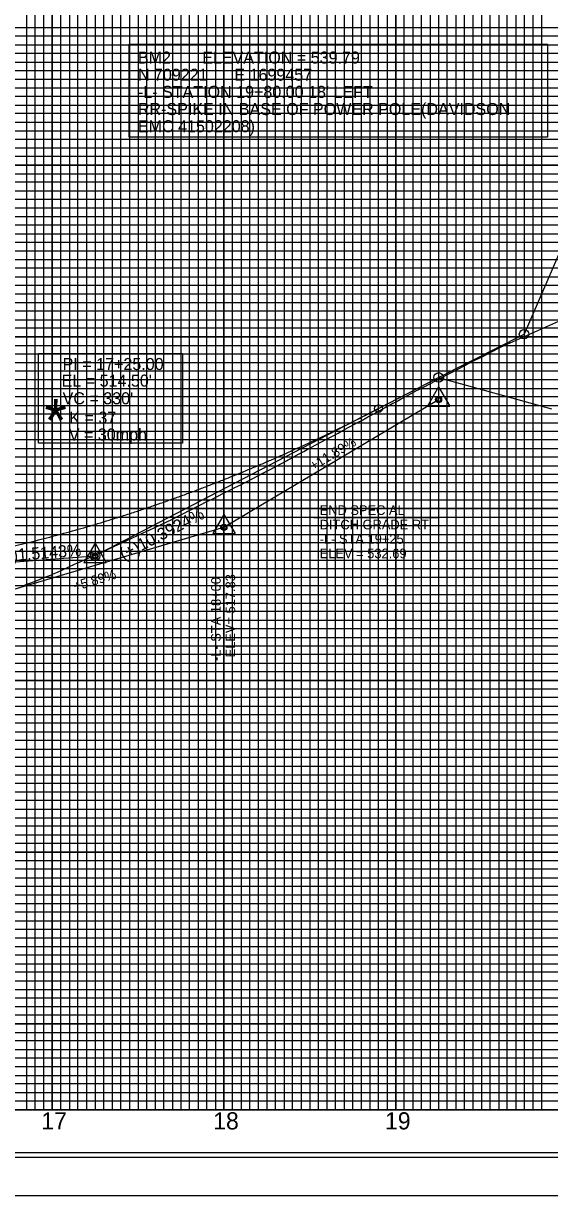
# Model space of a CAD drawing. Extents: x 573715 to 575626, y -55474 to -54374.
# Drawn here: x 574666 to 574972, y -55474 to -54792 of the extents above; entities that cross this region are included whole.
import ezdxf

# ---------------------------------------------------------------- set-up
doc = ezdxf.new("R2010")
doc.units = 0
for name, color, linetype in [('Exist Profile Cell', 7, 'Continuous'), ('Exist Vertical Profile Ground Line', 7, 'Continuous'), ('Exist Vertical Profile Horizontal Axis Label Major', 7, 'Continuous'), ('Prop Grid Mask', 7, 'Continuous'), ('Prop PFL VPI Symbol CELL', 7, 'Continuous'), ('Prop Vertical Profile Curve Label', 7, 'Continuous'), ('Prop Vertical Profile Ditch Grade Right', 7, 'Continuous'), ('Prop Vertical Profile Ditch Grade Right Label', 7, 'Continuous'), ('Prop Vertical Profile Grade', 7, 'Continuous'), ('Prop Vertical Profile Grade Label', 7, 'Continuous'), ('Prop VPI Label', 7, 'Continuous'), ('Sheet Cutting Line CELL', 7, 'Continuous'), ('Sheet DOT Grid CELL', 7, 'Continuous'), ('Sheet Layout Profile Border', 7, 'Continuous'), ('Sheet Plot Border Inside CELL', 7, 'Continuous'), ('Sheet Plot Border Outside CELL', 7, 'Continuous'), ('Sheet Profile CELL', 7, 'Continuous'), ('Sheet Profile Grid Major CELL', 7, 'Continuous'), ('Sheet Profile Grid Middle CELL', 7, 'Continuous'), ('Sheet Profile Grid Minor CELL', 7, 'Continuous')]:
    doc.layers.add(name, color=color, linetype=linetype)

msp = doc.modelspace()

# ---------------------------------------------------------------- linework, layer by layer
at = {"layer": 'Exist Profile Cell'}
msp.add_line((573982.27, -55224.42), (575001.21, -55224.42), dxfattribs=at)
at = {"layer": 'Exist Vertical Profile Ground Line'}
msp.add_lwpolyline([(574665.23, -55119.33), (574668.57, -55118.05), (574671.9, -55116.77), (574675.24, -55115.49), (574678.63, -55114.2), (574681.91, -55112.92), (574682.44, -55112.68), (574685.25, -55111.4), (574687.87, -55110.2), (574688.58, -55109.88), (574690.78, -55108.89), (574691.92, -55108.37), (574695.26, -55106.86), (574698.59, -55105.35), (574701.93, -55103.84), (574705.27, -55102.33), (574708.6, -55100.83), (574711.94, -55099.33), (574715.28, -55097.84), (574717.75, -55096.73), (574718.19, -55096.52), (574718.61, -55096.32), (574721.95, -55094.75), (574725.29, -55093.17), (574728.62, -55091.6), (574731.96, -55090.03), (574735.3, -55088.47), (574738.63, -55086.91), (574741.97, -55085.35), (574745.3, -55083.79), (574748.93, -55082.11), (574751.98, -55080.68), (574752.68, -55080.32), (574755.31, -55078.98), (574758.65, -55077.29), (574761.99, -55075.6), (574762.9, -55075.14), (574765.45, -55073.85), (574768.66, -55072.22), (574772, -55070.54), (574775.33, -55068.87), (574778.67, -55067.19), (574782.01, -55065.52), (574785.34, -55063.85), (574788.68, -55062.19), (574792.02, -55060.52), (574792.76, -55060.15), (574795.35, -55058.79), (574798.69, -55057.03), (574802.03, -55055.28), (574805.36, -55053.53), (574808.7, -55051.78), (574812.03, -55050.04), (574815.37, -55048.3), (574818.71, -55046.56), (574819.27, -55046.27), (574822.04, -55044.8), (574822.51, -55044.54), (574825.38, -55042.99), (574828.72, -55041.18), (574830.82, -55040.05), (574832.05, -55039.37), (574832.74, -55039), (574835.39, -55037.57), (574838.73, -55035.77), (574842.06, -55033.98), (574845.4, -55032.19), (574848.74, -55030.4), (574852.07, -55028.61), (574855.41, -55026.83), (574858.75, -55025.05), (574860.89, -55023.9), (574862.08, -55023.25), (574865.42, -55021.43), (574866.13, -55021.04), (574868.76, -55019.61), (574872.09, -55017.79), (574875.43, -55015.97), (574878.76, -55014.16), (574880.68, -55013.12), (574882.1, -55012.36), (574885.44, -55010.57), (574888.77, -55008.77), (574892.11, -55006.98), (574894.85, -55005.51), (574895.45, -55005.19), (574898.78, -55003.46), (574902.12, -55001.73), (574905.46, -55000), (574908.79, -54998.27), (574912.13, -54996.54), (574912.53, -54996.33), (574913.13, -54996.03), (574915.47, -54994.81), (574918.8, -54993.08), (574922.14, -54991.35), (574925.48, -54989.62), (574928.81, -54987.88), (574932.15, -54986.15), (574935.48, -54984.42), (574938.82, -54982.68), (574942.16, -54980.95), (574942.49, -54980.77), (574942.95, -54980.54), (574945.49, -54979.41), (574959.5, -54973.2), (574959.85, -54973.04), (574989.51, -54959.89)], dxfattribs=at)
at = {"layer": 'Prop Grid Mask'}
for points in [[(574727.11, -54803.99), (574970.69, -54803.99), (574970.69, -54858.09), (574727.11, -54858.09)], [(574674.23, -54984.04), (574758.07, -54984.04), (574758.07, -55036.29), (574674.23, -55036.29)]]:
    msp.add_lwpolyline(points, close=True, dxfattribs=at)
at = {"layer": 'Prop PFL VPI Symbol CELL'}
for p, q in [((574707.22, -55094.57), (574700.77, -55105.77)), ((574707.22, -55094.57), (574713.72, -55105.77)), ((574700.77, -55105.77), (574713.72, -55105.77))]:
    msp.add_line(p, q, dxfattribs=at)
for radius in [1.75, 1.2]:
    msp.add_circle((574707.23, -55102.05), radius, dxfattribs=at)
at = {"layer": 'Prop Vertical Profile Curve Label'}
for p, q in [((574987.75, -54901.88), (574957.02, -54972.88)), ((574907.27, -54998.02), (574973.06, -55016.41))]:
    msp.add_line(p, q, dxfattribs=at)
msp.add_circle((574872.27, -55016.18), 2.25, dxfattribs=at)
at = {"layer": 'Prop Vertical Profile Ditch Grade Right'}
msp.add_lwpolyline([(574506.27, -55216.92), (574632.27, -55129.42), (574782.27, -55085.27), (574907.27, -55010.97)], dxfattribs=at)
at = {"layer": 'Prop Vertical Profile Ditch Grade Right Label'}
for p, q in [((574907.27, -55003.49), (574900.82, -55014.69)), ((574907.27, -55003.49), (574913.77, -55014.69)), ((574900.82, -55014.69), (574913.77, -55014.69)), ((574907.27, -55010.97), (574907.27, -55079.52)), ((574782.27, -55077.79), (574775.82, -55088.99)), ((574782.27, -55077.79), (574788.77, -55088.99)), ((574834.62, -55079.52), (574907.27, -55079.52)), ((574775.82, -55088.99), (574788.77, -55088.99)), ((574782.27, -55085.27), (574782.27, -55164.71))]:
    msp.add_line(p, q, dxfattribs=at)
for centre, radius in [((574907.27, -55010.97), 1.75), ((574907.27, -55010.97), 1.2), ((574782.27, -55085.27), 1.75), ((574782.27, -55085.27), 1.2)]:
    msp.add_circle(centre, radius, dxfattribs=at)
at = {"layer": 'Prop Vertical Profile Grade'}
for p, q in [((574907.27, -54998), (574957.02, -54972.88)), ((574872.27, -55016.18), (574907.27, -54998))]:
    msp.add_line(p, q, dxfattribs=at)
msp.add_spline([(574542.27, -55114.41), (574548.87, -55113.88), (574555.47, -55113.3), (574562.07, -55112.65), (574568.67, -55111.95), (574575.27, -55111.18), (574581.87, -55110.36), (574588.47, -55109.48), (574595.07, -55108.54), (574601.67, -55107.54), (574608.27, -55106.49), (574614.87, -55105.37), (574621.47, -55104.2), (574628.07, -55102.97), (574634.67, -55101.68), (574641.27, -55100.33), (574647.87, -55098.92), (574654.47, -55097.45), (574661.07, -55095.93), (574667.67, -55094.34), (574674.27, -55092.7), (574680.87, -55091), (574687.47, -55089.24), (574694.07, -55087.42), (574700.67, -55085.54), (574707.27, -55083.61), (574713.87, -55081.62), (574720.47, -55079.56), (574727.07, -55077.45), (574733.67, -55075.28), (574740.27, -55073.05), (574746.87, -55070.77), (574753.47, -55068.42), (574760.07, -55066.02), (574766.67, -55063.56), (574773.27, -55061.03), (574779.87, -55058.45), (574786.47, -55055.82), (574793.07, -55053.12), (574799.67, -55050.36), (574806.27, -55047.55), (574812.87, -55044.68), (574819.47, -55041.74), (574826.07, -55038.75), (574832.67, -55035.71), (574839.27, -55032.6), (574845.87, -55029.43), (574852.47, -55026.21), (574859.07, -55022.93), (574865.67, -55019.58), (574872.27, -55016.18)], degree=3, dxfattribs=at)
at = {"layer": 'Prop VPI Label'}
for p, q in [((574872.27, -55016.18), (574709.71, -55100.65)), ((574542.27, -55114.41), (574704.53, -55102.13))]:
    msp.add_line(p, q, dxfattribs=at)
for centre in [(574957.02, -54972.88), (574907.27, -54998), (574907.27, -54998.02), (574707.27, -55101.92)]:
    msp.add_circle(centre, 2.75, dxfattribs=at)
at = {"layer": 'Sheet Cutting Line CELL'}
msp.add_line((573715.27, -55474.42), (575399.27, -55474.42), dxfattribs=at)
at = {"layer": 'Sheet DOT Grid CELL'}
for p, q in [((574682.27, -54399.42), (574682.27, -55424.42)), ((574732.27, -54399.42), (574732.27, -55424.42)), ((574782.27, -54399.42), (574782.27, -55424.42)), ((574832.27, -54399.42), (574832.27, -55424.42)), ((574882.27, -54399.42), (574882.27, -55424.42)), ((574932.27, -54399.42), (574932.27, -55424.42)), ((573882.27, -54824.42), (575382.27, -54824.42)), ((573882.27, -54874.42), (575382.27, -54874.42)), ((573882.27, -54924.42), (575382.27, -54924.42)), ((573882.27, -54974.42), (575382.27, -54974.42)), ((573882.27, -55024.42), (575382.27, -55024.42)), ((573882.27, -55074.42), (575382.27, -55074.42)), ((573882.27, -55124.42), (575382.27, -55124.42)), ((573882.27, -55174.42), (575382.27, -55174.42)), ((573882.27, -55224.42), (575382.27, -55224.42)), ((573882.27, -55274.42), (575382.27, -55274.42)), ((573882.27, -55324.42), (575382.27, -55324.42)), ((573882.27, -55374.42), (575382.27, -55374.42))]:
    msp.add_line(p, q, dxfattribs=at)
at = {"layer": 'Sheet Layout Profile Border'}
msp.add_lwpolyline([(573932.27, -54399.42), (573932.27, -55424.42), (575332.27, -55424.42), (575332.27, -54536.97), (575182.22, -54536.97), (575182.22, -54399.42)], close=True, dxfattribs=at)
at = {"layer": 'Sheet Plot Border Inside CELL'}
msp.add_lwpolyline([(575394.77, -54396.87), (573728.27, -54396.87), (573728.27, -55451.97), (575394.77, -55451.97)], close=True, dxfattribs=at)
msp.add_lwpolyline([(575394.77, -54396.87), (573728.27, -54396.87), (573728.27, -55451.97), (575394.77, -55451.97)], close=True, dxfattribs=at)
at = {"layer": 'Sheet Plot Border Outside CELL'}
msp.add_lwpolyline([(575399.27, -54374.42), (573715.27, -54374.42), (573715.27, -55474.42), (575399.27, -55474.42)], close=True, dxfattribs=at)
at = {"layer": 'Sheet Profile CELL'}
msp.add_line((575382.27, -55424.42), (573882.27, -55424.42), dxfattribs=at)
msp.add_lwpolyline([(575382.27, -54399.42), (573882.27, -54399.42), (573882.27, -55449.42), (575382.27, -55449.42)], close=True, dxfattribs=at)
at = {"layer": 'Sheet Profile Grid Major CELL'}
for points in [[(574632.27, -54399.42), (574632.27, -55424.42), (574682.27, -55424.42), (574682.27, -54399.42)], [(574732.27, -54399.42), (574732.27, -55424.42), (574782.27, -55424.42), (574782.27, -54399.42)], [(574832.27, -54399.42), (574832.27, -55424.42), (574882.27, -55424.42), (574882.27, -54399.42)], [(574932.27, -54399.42), (574932.27, -55424.42), (574982.27, -55424.42)], [(575382.27, -54874.42), (573882.27, -54874.42), (573882.27, -54824.42), (575382.27, -54824.42)], [(575382.27, -54974.42), (573882.27, -54974.42), (573882.27, -54924.42), (575382.27, -54924.42)], [(575382.27, -55074.42), (573882.27, -55074.42), (573882.27, -55024.42), (575382.27, -55024.42)], [(575382.27, -55174.42), (573882.27, -55174.42), (573882.27, -55124.42), (575382.27, -55124.42)], [(575382.27, -55274.42), (573882.27, -55274.42), (573882.27, -55224.42), (575382.27, -55224.42)], [(575382.27, -55374.42), (573882.27, -55374.42), (573882.27, -55324.42), (575382.27, -55324.42)]]:
    msp.add_lwpolyline(points, dxfattribs=at)
at = {"layer": 'Sheet Profile Grid Middle CELL'}
for points in [[(574707.27, -54399.42), (574707.27, -55424.42), (574757.27, -55424.42), (574757.27, -54399.42)], [(574807.27, -54399.42), (574807.27, -55424.42), (574857.27, -55424.42), (574857.27, -54399.42)], [(574907.27, -54399.42), (574907.27, -55424.42), (574957.27, -55424.42), (574957.27, -54399.42)], [(575382.27, -54799.42), (573882.27, -54799.42), (573882.27, -54849.42), (575382.27, -54849.42)], [(575382.27, -54899.42), (573882.27, -54899.42), (573882.27, -54949.42), (575382.27, -54949.42)], [(575382.27, -54999.42), (573882.27, -54999.42), (573882.27, -55049.42), (575382.27, -55049.42)], [(575382.27, -55099.42), (573882.27, -55099.42), (573882.27, -55149.42), (575382.27, -55149.42)], [(575382.27, -55199.42), (573882.27, -55199.42), (573882.27, -55249.42), (575382.27, -55249.42)], [(575382.27, -55299.42), (573882.27, -55299.42), (573882.27, -55349.42), (575382.27, -55349.42)], [(575382.27, -55399.42), (573882.27, -55399.42)]]:
    msp.add_lwpolyline(points, dxfattribs=at)
at = {"layer": 'Sheet Profile Grid Minor CELL'}
for points in [[(574667.27, -54399.42), (574667.27, -55424.42), (574672.27, -55424.42), (574672.27, -54399.42)], [(574677.27, -54399.42), (574677.27, -55424.42), (574687.27, -55424.42), (574687.27, -54399.42)], [(574692.27, -54399.42), (574692.27, -55424.42), (574697.27, -55424.42), (574697.27, -54399.42)], [(574702.27, -54399.42), (574702.27, -55424.42), (574712.27, -55424.42), (574712.27, -54399.42)], [(574717.27, -54399.42), (574717.27, -55424.42), (574722.27, -55424.42), (574722.27, -54399.42)], [(574727.27, -54399.42), (574727.27, -55424.42), (574737.27, -55424.42), (574737.27, -54399.42)], [(574742.27, -54399.42), (574742.27, -55424.42), (574747.27, -55424.42), (574747.27, -54399.42)], [(574752.27, -54399.42), (574752.27, -55424.42), (574762.27, -55424.42), (574762.27, -54399.42)], [(574767.27, -54399.42), (574767.27, -55424.42), (574772.27, -55424.42), (574772.27, -54399.42)], [(574777.27, -54399.42), (574777.27, -55424.42), (574787.27, -55424.42), (574787.27, -54399.42)], [(574792.27, -54399.42), (574792.27, -55424.42), (574797.27, -55424.42), (574797.27, -54399.42)], [(574802.27, -54399.42), (574802.27, -55424.42), (574812.27, -55424.42), (574812.27, -54399.42)], [(574817.27, -54399.42), (574817.27, -55424.42), (574822.27, -55424.42), (574822.27, -54399.42)], [(574827.27, -54399.42), (574827.27, -55424.42), (574837.27, -55424.42), (574837.27, -54399.42)], [(574842.27, -54399.42), (574842.27, -55424.42), (574847.27, -55424.42), (574847.27, -54399.42)], [(574852.27, -54399.42), (574852.27, -55424.42), (574862.27, -55424.42), (574862.27, -54399.42)], [(574867.27, -54399.42), (574867.27, -55424.42), (574872.27, -55424.42), (574872.27, -54399.42)], [(574877.27, -54399.42), (574877.27, -55424.42), (574887.27, -55424.42), (574887.27, -54399.42)], [(574892.27, -54399.42), (574892.27, -55424.42), (574897.27, -55424.42), (574897.27, -54399.42)], [(574902.27, -54399.42), (574902.27, -55424.42), (574912.27, -55424.42), (574912.27, -54399.42)], [(574917.27, -54399.42), (574917.27, -55424.42), (574922.27, -55424.42), (574922.27, -54399.42)], [(574927.27, -54399.42), (574927.27, -55424.42), (574937.27, -55424.42), (574937.27, -54399.42)], [(574942.27, -54399.42), (574942.27, -55424.42), (574947.27, -55424.42), (574947.27, -54399.42)], [(574952.27, -54399.42), (574952.27, -55424.42)], [(574952.27, -55424.42), (574962.27, -55424.42), (574962.27, -54399.42), (574967.27, -54399.42), (574967.27, -55424.42), (574972.27, -55424.42)], [(575332.27, -54794.42), (573932.27, -54794.42), (573932.27, -54804.42), (575332.27, -54804.42)], [(575332.27, -54809.42), (573932.27, -54809.42), (573932.27, -54814.42), (575332.27, -54814.42)], [(575332.27, -54819.42), (573932.27, -54819.42), (573932.27, -54829.42), (575332.27, -54829.42)], [(575332.27, -54834.42), (573932.27, -54834.42), (573932.27, -54839.42), (575332.27, -54839.42)], [(575332.27, -54844.42), (573932.27, -54844.42), (573932.27, -54854.42), (575332.27, -54854.42)], [(575332.27, -54859.42), (573932.27, -54859.42), (573932.27, -54864.42), (575332.27, -54864.42)], [(575332.27, -54869.42), (573932.27, -54869.42), (573932.27, -54879.42), (575332.27, -54879.42)], [(575332.27, -54884.42), (573932.27, -54884.42), (573932.27, -54889.42), (575332.27, -54889.42)], [(575332.27, -54894.42), (573932.27, -54894.42), (573932.27, -54904.42), (575332.27, -54904.42)], [(575332.27, -54909.42), (573932.27, -54909.42), (573932.27, -54914.42), (575332.27, -54914.42)], [(575332.27, -54919.42), (573932.27, -54919.42)], [(573932.27, -54929.42), (575332.27, -54929.42)], [(575332.27, -54934.42), (573932.27, -54934.42), (573932.27, -54939.42), (575332.27, -54939.42)], [(575332.27, -54944.42), (573932.27, -54944.42), (573932.27, -54954.42), (575332.27, -54954.42)], [(575332.27, -54959.42), (573932.27, -54959.42), (573932.27, -54964.42), (575332.27, -54964.42)], [(575332.27, -54969.42), (573932.27, -54969.42), (573932.27, -54979.42), (575332.27, -54979.42)], [(575332.27, -54984.42), (573932.27, -54984.42), (573932.27, -54989.42), (575332.27, -54989.42)], [(575332.27, -54994.42), (573932.27, -54994.42), (573932.27, -55004.42), (575332.27, -55004.42)], [(575332.27, -55009.42), (573932.27, -55009.42), (573932.27, -55014.42), (575332.27, -55014.42)], [(575332.27, -55019.42), (573932.27, -55019.42), (573932.27, -55029.42), (575332.27, -55029.42)], [(575332.27, -55034.42), (573932.27, -55034.42), (573932.27, -55039.42), (575332.27, -55039.42)], [(575332.27, -55044.42), (573932.27, -55044.42), (573932.27, -55054.42), (575332.27, -55054.42)], [(575332.27, -55059.42), (573932.27, -55059.42), (573932.27, -55064.42), (575332.27, -55064.42)], [(575332.27, -55069.42), (573932.27, -55069.42), (573932.27, -55079.42), (575332.27, -55079.42)], [(575332.27, -55084.42), (573932.27, -55084.42), (573932.27, -55089.42), (575332.27, -55089.42)], [(575332.27, -55094.42), (573932.27, -55094.42), (573932.27, -55104.42), (575332.27, -55104.42)], [(575332.27, -55109.42), (573932.27, -55109.42), (573932.27, -55114.42), (575332.27, -55114.42)], [(575332.27, -55119.42), (573932.27, -55119.42), (573932.27, -55129.42), (575332.27, -55129.42)], [(575332.27, -55134.42), (573932.27, -55134.42), (573932.27, -55139.42), (575332.27, -55139.42)], [(575332.27, -55144.42), (573932.27, -55144.42), (573932.27, -55154.42), (575332.27, -55154.42)], [(575332.27, -55159.42), (573932.27, -55159.42), (573932.27, -55164.42), (575332.27, -55164.42)], [(575332.27, -55169.42), (573932.27, -55169.42), (573932.27, -55179.42), (575332.27, -55179.42)], [(575332.27, -55184.42), (573932.27, -55184.42), (573932.27, -55189.42), (575332.27, -55189.42)], [(575332.27, -55194.42), (573932.27, -55194.42), (573932.27, -55204.42), (575332.27, -55204.42)], [(575332.27, -55209.42), (573932.27, -55209.42), (573932.27, -55214.42), (575332.27, -55214.42)], [(575332.27, -55219.42), (573932.27, -55219.42)], [(573932.27, -55229.42), (575332.27, -55229.42)], [(575332.27, -55234.42), (573932.27, -55234.42), (573932.27, -55239.42), (575332.27, -55239.42)], [(575332.27, -55244.42), (573932.27, -55244.42)], [(573932.27, -55254.42), (575332.27, -55254.42)], [(575332.27, -55259.42), (573932.27, -55259.42), (573932.27, -55264.42), (575332.27, -55264.42)], [(575332.27, -55269.42), (573932.27, -55269.42), (573932.27, -55279.42), (575332.27, -55279.42)], [(575332.27, -55284.42), (573932.27, -55284.42), (573932.27, -55289.42), (575332.27, -55289.42)], [(575332.27, -55294.42), (573932.27, -55294.42), (573932.27, -55304.42), (575332.27, -55304.42)], [(575332.27, -55309.42), (573932.27, -55309.42), (573932.27, -55314.42), (575332.27, -55314.42)], [(575332.27, -55319.42), (573932.27, -55319.42), (573932.27, -55329.42), (575332.27, -55329.42)], [(575332.27, -55334.42), (573932.27, -55334.42), (573932.27, -55339.42), (575332.27, -55339.42)], [(575332.27, -55344.42), (573932.27, -55344.42), (573932.27, -55354.42), (575332.27, -55354.42)], [(575332.27, -55359.42), (573932.27, -55359.42), (573932.27, -55364.42), (575332.27, -55364.42)], [(575332.27, -55369.42), (573932.27, -55369.42), (573932.27, -55379.42), (575332.27, -55379.42)], [(575332.27, -55384.42), (573932.27, -55384.42), (573932.27, -55389.42), (575332.27, -55389.42)], [(575332.27, -55394.42), (573932.27, -55394.42), (573932.27, -55404.42), (575332.27, -55404.42)], [(575332.27, -55409.42), (573932.27, -55409.42), (573932.27, -55414.42), (575332.27, -55414.42)], [(575332.27, -55419.42), (573932.27, -55419.42)]]:
    msp.add_lwpolyline(points, dxfattribs=at)

# ---------------------------------------------------------------- texts
at = {"layer": 'Exist Vertical Profile Horizontal Axis Label Major'}
for s, p in [('18', (574776.04, -55435.92)), ('19', (574876.08, -55435.92)), ('17', (574675.92, -55435.92))]:
    msp.add_text(s, height=10, dxfattribs=at).set_placement(p)
at = {"layer": 'Prop Vertical Profile Curve Label'}
for s, p in [("VC = 330'", (574688.32, -55013.68)), ('K = 37', (574692.23, -55024.97)), ('V = 30mph', (574691.92, -55034.77))]:
    msp.add_text(s, height=7, dxfattribs=at).set_placement(p)
at = {"layer": 'Prop Vertical Profile Ditch Grade Right'}
for s, rotation, p in [('+11.89%', 30.72725, (574834.21, -55052.47)), ('+5.89%', 16.9943, (574695.56, -55122.55))]:
    msp.add_text(s, height=5.6, rotation=rotation, dxfattribs=at).set_placement(p)
at = {"layer": 'Prop Vertical Profile Ditch Grade Right Label'}
for s, p in [('END SPECIAL', (574838.01, -55078.11)), ('DITCH GRADE RT', (574838.01, -55086.51)), ('-L- STA 19+25', (574838.01, -55094.91)), ('ELEV = 532.69', (574838.01, -55103.31))]:
    msp.add_text(s, height=5.6, dxfattribs=at).set_placement(p)
for s, p in [('-L- STA 18+00', (574780.4, -55163.17)), (' ELEV= 517.83', (574788.8, -55163.17))]:
    msp.add_text(s, height=5.6, rotation=90, dxfattribs=at).set_placement(p)
at = {"layer": 'Prop Vertical Profile Grade Label'}
for s, rotation, p in [('(+)10.3924%', 27.45729, (574723.76, -55104.62)), ('(+)1.5143%', 4.32985, (574650.88, -55105.62))]:
    msp.add_text(s, height=7, rotation=rotation, dxfattribs=at).set_placement(p)
at = {"layer": 'Prop VPI Label'}
for s, height, p in [("BM2       ELEVATION = 539.79'", 7, (574732.15, -54815.27)), ('N 709221      E 1699457', 7, (574732.15, -54825.27)), ("-L- STATION 19+80.00 18' LEFT", 7, (574732.15, -54835.27)), ('RR-SPIKE IN BASE OF POWER POLE(DAVIDSON', 7, (574732.15, -54845.27)), ('EMC 41502208)', 7, (574732.15, -54855.27)), ('PI = 17+25.00', 7, (574688.32, -54993.73)), ("EL = 514.50'", 7, (574687.76, -55003.4)), ('*', 25, (574677.77, -55035.62))]:
    msp.add_text(s, height=height, dxfattribs=at).set_placement(p)

doc.saveas('drawing.dxf')
